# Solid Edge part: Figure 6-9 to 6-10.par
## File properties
Accuracy: 0.99
Author: CADCIM
Template: normal.par
Last saved by: Ashutosh-CADCIM
Revision: 8
Application: Solid Edge
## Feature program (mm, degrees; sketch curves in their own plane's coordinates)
sketch for "unnamed Protrusion 1" plane through (0, 0, 0) normal (0, 0, 1) x-axis (1, 0, 0)
  line (-22.8701, -37.8701) -> (22.8701, -37.8701)
  arc centre (22.8701, -22.8701) radius 15 from (22.8701, -37.8701) to (37.8701, -22.8701) ccw
  line (37.8701, -22.8701) -> (37.8701, 22.8701)
  arc centre (22.8701, 22.8701) radius 15 from (37.8701, 22.8701) to (22.8701, 37.8701) ccw
  line (22.8701, 37.8701) -> (-22.8701, 37.8701)
  arc centre (-22.8701, 22.8701) radius 15 from (-22.8701, 37.8701) to (-37.8701, 22.8701) ccw
  line (-37.8701, 22.8701) -> (-37.8701, -22.8701)
  arc centre (-22.8701, -22.8701) radius 15 from (-22.8701, -37.8701) to (-37.8701, -22.8701) cw
extrude "unnamed Protrusion 1" add finite 20 along +normal
sketch for "Hole_3" plane through (0, 0, 20) normal (0, 0, 1) x-axis (0, 1, 0)
  hole centre (-22.8701, 22.8701) bore radius 4.5
hole "Hole_3" diameter 9 finite  CounterBoreDepth = 5 mm
sketch for "unnamed Hole 1" plane through (0, 0, 20) normal (0, 0, 1) x-axis (0, 1, 0)
  hole centre (22.8701, 22.8701) bore radius 4.5
hole "unnamed Hole 1" finite
sketch for "unnamed Hole 2" plane through (0, 0, 20) normal (0, 0, 1) x-axis (0, 1, 0)
  hole centre (22.8701, -22.8701) bore radius 4.5
hole "unnamed Hole 2" finite
sketch for "unnamed Hole 3" plane through (0, 0, 20) normal (0, 0, 1) x-axis (0, 1, 0)
  hole centre (-22.8701, -22.8701) bore radius 4.5
hole "unnamed Hole 3" finite
pattern "unnamed Pattern 1" of "Hole_3", "unnamed Hole 1", "unnamed Hole 2", "unnamed Hole 3"
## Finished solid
Body 1: solid body, 22 faces, 40 edges, 16 vertices.
  Faces by surface: cylinder 12, plane 10
  Edges by curve: circle 24, line 16
Bounding box of the edges (mm): 75.740 x 75.740 x 20.000, from (-37.8701, -37.8701, 0) to (37.8701, 37.8701, 20).
Cylindrical faces by radius (mm): R4.5 x4, R7.5 x4, R15 x4
Planar faces by outward normal: +x 1, +y 1, +z 5, -x 1, -y 1, -z 1
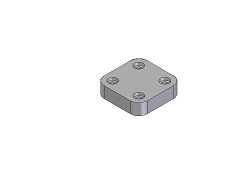
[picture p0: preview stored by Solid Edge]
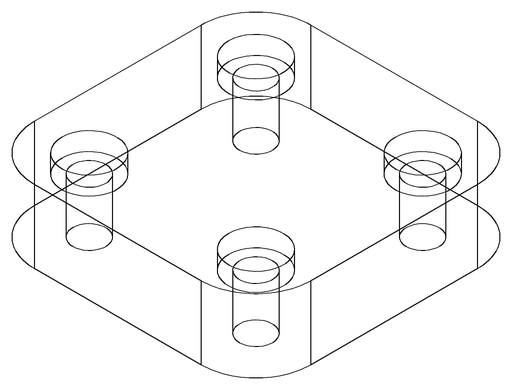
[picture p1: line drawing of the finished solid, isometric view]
